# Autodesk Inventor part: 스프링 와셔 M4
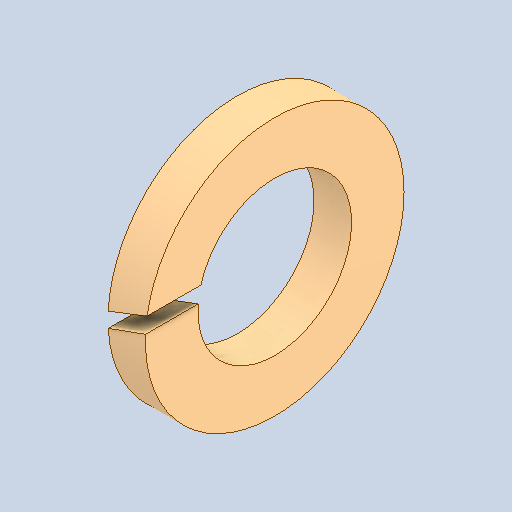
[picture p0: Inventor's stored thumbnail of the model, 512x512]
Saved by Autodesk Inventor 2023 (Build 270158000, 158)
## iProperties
Created: 2026-03
Part Number: 스프링 와셔 M4
Material: 강철, 연강
Description: 스프링 잠금 와셔
Document SubType Name: Modeling
Designer: 4강의실
Density: 7.85 g/cm^3
Appearance: 기본값
Author: jhkim
Sending System: Autodesk Inventor 2026
Preprocessor: ST-DEVELOPER v20.1
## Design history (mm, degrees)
feature "Solid1"
node "솔리드1"
